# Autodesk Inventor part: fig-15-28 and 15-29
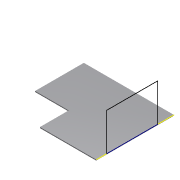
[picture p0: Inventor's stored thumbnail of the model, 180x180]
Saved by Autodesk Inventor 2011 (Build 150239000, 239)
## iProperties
Created: 2005-03
Part Number: fig-15-28 and 15-29
Document SubType Name: Sheet Metal
Designer: CADCIM
Manufacturer: Standard
Standards Organization: Custom
Density: 1 g/cm^3
Sheet Metal Rule: Default
Author: CADCIM
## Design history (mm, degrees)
node "Face1"
  sketch "Sketch1"
    geometry: L1 (29.25, 32.25)-(-19.875, 32.25); L2 (-19.875, 32.25)-(-19.875, 5.625); L3 (-19.875, 5.625)-(-1.5, 5.625); L4 (-1.5, 5.625)-(-1.5, -10.125); L5 (-1.5, -10.125)-(29.25, -10.125); L6 (29.25, -10.125)-(29.25, 32.25)
    constraints: 12 end point, 4 parallel, 1 horizontal, 1 perpendicular
sketch "Sketch2"
  geometry: L1 (-0.5, 42.375)-(-0.5, 0) reference; L2 (-0.5, 5.593)-(-21.049, 5.593); L3 (-21.049, 5.593)-(-21.049, 33.56); L4 (-21.049, 33.56)-(-0.5, 33.56); L5 (-0.5, 33.56)-(-0.5, 5.593)
  constraints: 8 end point, 2 parallel, 1 horizontal, 1 perpendicular, 1 point on line
body "Solid1"
face "Plate1" dims "Thickness" = 0.5
other parameters: "BendRadius" = 0.5 (= Thickness), "BendReliefWidth" = 0.5 (= Thickness), "BendReliefDepth" = 0.25 (= 0.5 x Thickness), "CornerReliefSize" = 2 (= 4 x Thickness), "SeamGap" = 0.01, "MinimumRemnant" = 1 (= 2 x Thickness), "TransitionRadius" = 0.5 (= BendRadius), "d0" = 0.5 (= BendRadius), "JacobiRadiusSize" = 0.5 (= Thickness), "GapSize" = 0.5 (= Thickness)
